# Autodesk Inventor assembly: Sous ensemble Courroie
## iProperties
Created: 2004-11
Part Number: Sous ensemble Courroie
Document SubType Name: Assembly
Designer: Bruno
Manufacturer: Standard
Standards Organization: Custom
Norme de conversion: STEP AP203
Nom du fichier: Take Out.stp
Préprocesseur: Mechanical Desktop 2005
Postprocesseur: Build: 096e, Release: 9 RTM - Date: Thu 06/17/2004
Unités envoyées: MILLIMETERS
Incertitude: 1.0000000000000002e-06
Author: Bruno
